// Mitsubishi GX Works2 project: 4.混合控制   PLC: FX3U/FX3UC

PROGRAM MAIN
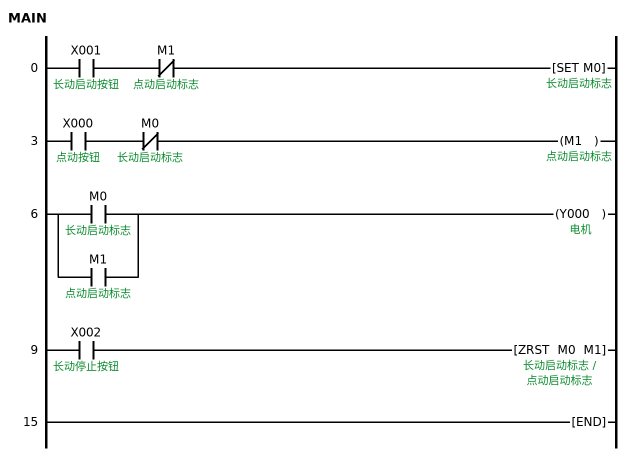
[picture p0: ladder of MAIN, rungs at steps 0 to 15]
0     LD      X001  ; 长动启动按钮
      ANI     M1  ; 点动启动标志
      SET     M0  ; 长动启动标志
3     LD      X000  ; 点动按钮
      ANI     M0  ; 长动启动标志
      OUT     M1  ; 点动启动标志
6     LD      M0  ; 长动启动标志
      OR      M1  ; 点动启动标志
      OUT     Y000  ; 电机
9     LD      X002  ; 长动停止按钮
      ZRST    M0 M1
15    END
END_PROGRAM
